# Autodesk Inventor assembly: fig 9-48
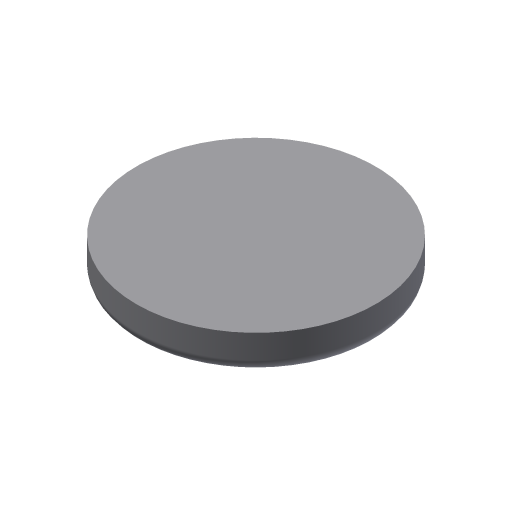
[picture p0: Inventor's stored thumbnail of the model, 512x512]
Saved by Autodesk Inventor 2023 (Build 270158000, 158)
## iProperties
Created: 2013-07
Part Number: fig 9-48
Document SubType Name: Assembly
Designer: CADCIM
Author: CADCIM
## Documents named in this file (3)
- D:\PROJECTS\Project 2022\Autodesk Inventor For Professional 2023\RESOURCES INVENTOR 2023\RESOURCES INVENTOR 2023\Inventor_2023_Part\Inventor_2023_Part\c09_Inv_2023_prt\fig 9-49.iam
- E:\_Deepak\Inventor\Autodesk Inventor_2017_Project\Resources\Inventor_2018_Part\c09_Inv_2018\c09_inv_2018_prt\17 (1).ipt
- D:\PROJECTS\Project 2022\Autodesk Inventor For Professional 2023\RESOURCES INVENTOR 2023\RESOURCES INVENTOR 2023\Inventor_2023_Part\Inventor_2023_Part\c09_Inv_2023_prt\18.ipt
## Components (2 placed, 2 different names)
1. 17 (1):1 — Planar:1
2. 18:1 — Planar:1
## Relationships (1: PlanarJoint 1)
- Planar:1: 17 (1):1 ↔ 18:1
